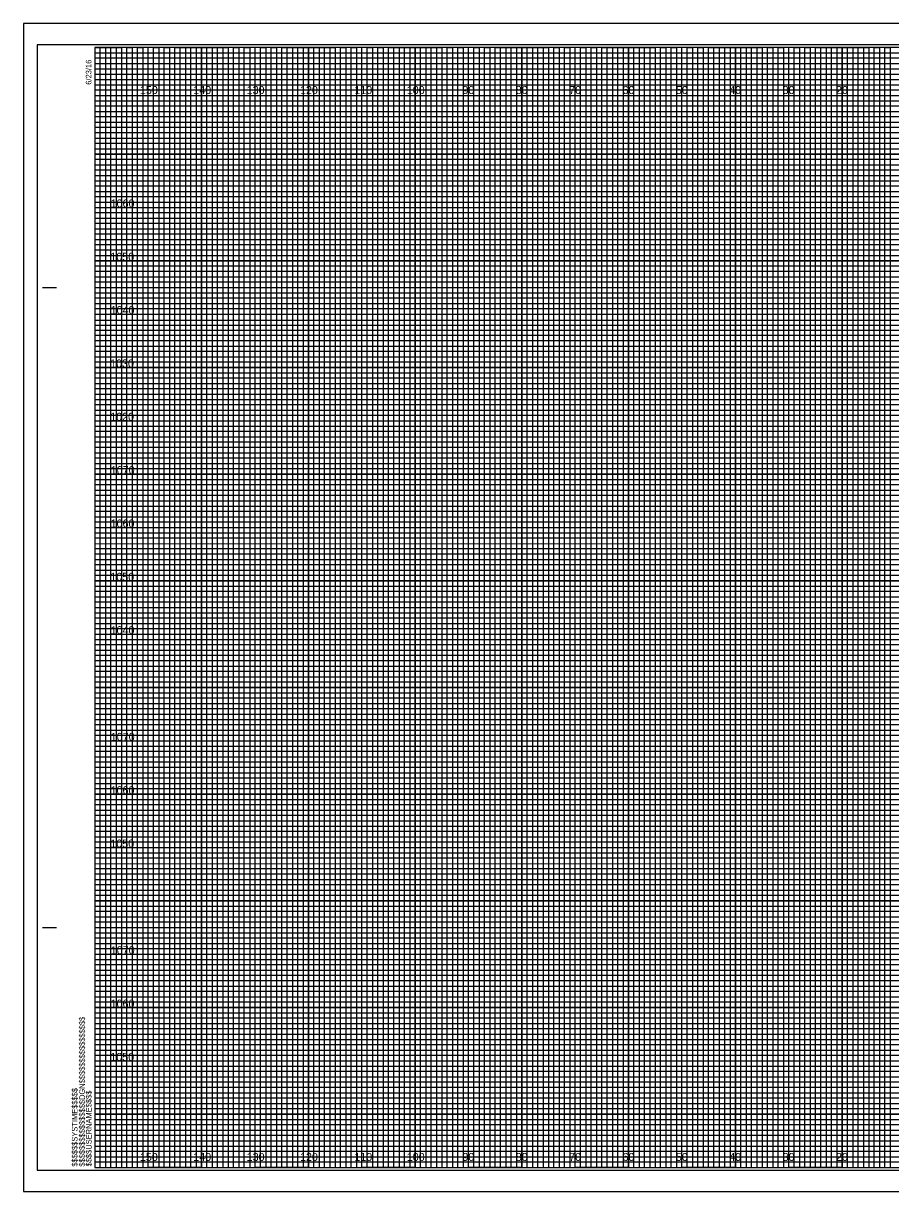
# Model space of a CAD drawing. Extents: x -13 to 323, y -5 to 215.
# Drawn here: x -13.4 to 149.1, y -4.5 to 214.5 of the extents above; entities that cross this region are included whole.
import ezdxf

# ---------------------------------------------------------------- set-up
doc = ezdxf.new("R2010")
doc.units = 0
for name, color, linetype in [('Exist Cross Section Cell', 7, 'Continuous'), ('Exist XS Center Line Elevation Label', 7, 'Continuous'), ('Exist XS Ground Line', 7, 'Continuous'), ('Prop CMT Conc Surface', 7, 'Continuous'), ('Prop CMT Concrete Structures', 7, 'Continuous'), ('Prop CMT Pvmt Course 1 CG', 7, 'Continuous'), ('Prop CMT Pvmt Course 2', 7, 'Continuous'), ('Prop CMT Pvmt Surface', 7, 'Continuous'), ('Prop CMT Slope Grass', 7, 'Continuous'), ('Prop CMT Subgrade Earthwork', 7, 'Continuous'), ('Scratch_Level_0', 7, 'Continuous')]:
    doc.layers.add(name, color=color, linetype=linetype)

msp = doc.modelspace()

# ---------------------------------------------------------------- linework, layer by layer
at = {"layer": 'Exist XS Ground Line'}
for p, q in [((323.3, 214.5), (-13.4, 214.5)), ((-13.4, 214.5), (-13.4, -4.5)), ((-13.4, -4.5), (323.3, -4.5))]:
    msp.add_line(p, q, dxfattribs=at)
at = {"layer": 'Prop CMT Conc Surface'}
msp.add_lwpolyline([(-13.4, -4.5), (323.3, -4.5), (323.3, 214.5), (-13.4, 214.5)], close=True, dxfattribs=at)
at = {"layer": 'Prop CMT Concrete Structures'}
for p, q in [((0, 209), (260, 209)), ((260, 207.98), (0, 207.98)), ((0, 207.98), (0, 207)), ((0, 207), (260, 207)), ((260, 205.89), (0, 205.89)), ((0, 205.89), (0, 204)), ((0, 204), (320, 204))]:
    msp.add_line(p, q, dxfattribs=at)
for points in [[(0, 203), (270, 203), (320, 203), (320, 202), (0, 202)], [(0, 201), (320, 201), (320, 199), (0, 199)], [(0, 198), (320, 198), (320, 197), (0, 196.98)], [(0, 196), (320, 196), (320, 194), (0, 194)], [(0, 193), (320, 193), (320, 192), (0, 192)], [(0, 191), (320, 191), (320, 189), (0, 189)], [(0, 188), (320, 188), (320, 187), (0, 187)], [(0, 186), (320, 186), (320, 184), (0, 184)], [(0, 183), (320, 183), (320, 182), (0, 182)], [(0, 181), (320, 181), (320, 179), (0, 179)], [(0, 178), (320, 178), (320, 177), (0, 177)], [(0, 176), (320, 176), (320, 173.95), (320, 173), (320, 172), (0, 172)], [(0, 174), (320, 174), (320, 173), (0, 173)], [(0, 171), (320, 171), (320, 169), (0, 169.03)], [(0, 169.03), (320, 169), (320, 168), (0, 168)], [(0, 167), (320, 167), (320, 166), (0, 166)], [(0, 164), (320, 164), (320, 163), (0, 163)], [(0, 162), (320, 162), (320, 161), (0, 161)], [(-0.07, 158.89), (320, 158.89), (320, 157.88), (-0.07, 157.88)], [(0, 157), (320, 157), (320, 156), (0, 156)], [(0, 154), (320, 154), (320, 153), (0, 153)], [(0, 152), (320, 152), (320, 151), (0, 151)], [(0, 149), (320, 149), (320, 148), (0, 148)], [(0, 147), (320, 147), (320, 146), (0, 146)], [(0, 144), (320, 144), (320, 143), (0, 143)], [(0, 142), (320, 142), (320, 141), (0, 141)], [(0, 139), (320, 139), (319.99, 137.98), (0, 138)], [(0, 137), (320, 137), (320, 136), (0, 136)], [(0, 134), (320, 134), (320, 133), (0, 133)], [(0, 132), (320, 132), (320, 131), (0, 131)], [(0, 129), (320, 129), (320, 128), (0, 128)], [(0, 127), (320, 127), (320, 126), (0, 126)], [(0, 124), (320, 124), (320, 123), (0, 123)], [(0, 122), (320, 122), (320, 121), (0, 121)], [(0, 119), (320, 119), (320, 118), (0, 118)], [(0, 116.99), (320.07, 116.91), (320, 116), (0, 116)], [(0, 114), (320, 114), (320, 113), (0, 113)], [(0, 112), (320, 112), (320, 111), (0, 111)], [(0, 109), (320, 109), (320, 108), (0, 108)], [(0, 107), (320, 107), (320, 106), (0, 106)], [(0, 104), (320, 104), (320, 103), (0, 103)], [(0, 102), (320, 102), (320, 101), (0, 101)], [(0, 99), (320, 99), (320, 98), (0, 98)], [(0, 97), (320, 97), (320, 96), (0, 96)], [(0, 94), (320, 94), (320, 93), (0, 93)], [(0, 92), (320, 92), (320, 91), (0, 91)], [(0, 89), (320, 89), (320, 88), (0, 88)], [(0, 87), (320, 87), (320, 86), (0, 86)], [(0, 84), (320, 84), (320, 83), (0, 83)], [(0, 82), (320, 82), (320, 81), (0, 81)], [(0, 79), (320, 79), (319.99, 77.98), (0, 78)], [(0, 77), (320, 77), (320, 76), (0, 76)], [(0, 74), (320, 74), (320, 73), (0, 73)], [(0, 72), (320, 72), (320, 71), (0, 71)], [(0, 69), (320, 69), (320, 68), (0, 68)], [(0, 67), (320, 67), (320, 66), (0, 66)], [(0, 64), (320, 64), (320, 63), (0, 63)], [(0, 62), (320, 62), (320, 61), (0, 61)], [(0, 59), (320, 59), (320, 58), (0, 58)], [(0, 56.99), (320.07, 56.91), (320, 56), (0, 56)], [(0, 54), (320, 54), (320, 53), (0, 53)], [(0, 52), (320, 52), (320, 51), (0, 51)], [(0, 49), (320, 49), (320, 48), (0, 48)], [(0, 47), (320, 47), (320, 46), (0, 46)], [(0, 44), (320, 44), (320, 43), (0, 43)], [(0, 42), (320, 42), (320, 41), (0, 41)], [(0, 39), (320, 39), (320, 38), (0, 38)], [(0, 37), (320, 37), (320, 36), (0, 36)], [(0, 34), (320, 34), (320, 33), (0, 33)], [(0, 32), (320, 32), (320, 31), (0, 31)], [(0, 29), (320, 29), (320, 28), (0, 28)], [(0, 27), (320, 27), (320, 26), (0, 26)], [(0, 24), (320, 24), (320, 23), (0, 23)], [(0, 22), (320, 22), (320, 21), (0, 21)], [(0, 19), (320, 19), (320, 18), (0, 18)], [(0, 17), (320, 17), (320, 16), (0, 16)], [(0, 14), (320, 14), (320, 13), (0, 13)], [(0, 12), (320, 12), (320, 11), (0, 11)], [(0, 9), (320, 9), (320, 8), (0, 8)], [(0, 7), (320, 7), (320, 6), (0, 6)], [(0, 4), (320, 4), (320, 3), (0, 3)], [(0, 2), (320, 2), (320, 1), (0, 1)]]:
    msp.add_lwpolyline(points, dxfattribs=at)
at = {"layer": 'Prop CMT Pvmt Course 1 CG'}
for points in [[(0, 0), (1, 0), (1, 210), (2, 210), (2, 0)], [(2, 0), (3, 0), (3, 210), (4, 210), (4, 0)], [(5, 0), (6, 0), (6, 210), (7, 210), (7, 0)], [(7, 0), (8, 0), (8, 210), (9, 210), (9, 0)], [(10, 0), (11, 0), (11, 210), (12, 210), (12, 0)], [(12, 0), (13, 0), (13, 210), (14, 210), (14, 0)], [(15, 0), (16, 0), (16, 210), (17, 210), (17, 0)], [(17, 0), (18, 0), (18, 210), (19, 210), (19, 0)], [(20, 0), (21, 0), (21, 210), (22, 210), (22, 0)], [(22, 0), (23, 0), (23, 210), (24, 210), (24, 0)], [(25, 0), (26, 0), (26, 210), (27, 210), (27, 0)], [(27, 0), (28, 0), (28, 210), (29, 210), (29, 0)], [(30, 0), (31, 0), (31, 210), (32, 210), (32, 0)], [(32, 0), (33, 0), (33, 210), (34, 210), (34, 0)], [(35, 0), (36, 0), (36, 210), (37, 210), (37, 0)], [(37, 0), (38, 0), (38, 210), (39, 210), (39, 0)], [(40, 0), (41, 0), (41, 210), (42, 210), (42, 0)], [(42, 0), (43, 0), (43, 210), (44, 210), (44, 0)], [(45, 0), (46, 0), (46, 210), (47, 210), (47, 0)], [(47, 0), (48, 0), (48, 210), (49, 210), (49, 0)], [(50, 0), (51, 0), (51, 210), (52, 210), (52, 0)], [(52, 0), (53, 0), (53, 210), (54, 210), (54, 0)], [(55, 0), (56, 0), (56, 210), (57, 210), (57, 0)], [(57, 0), (58, 0), (58, 210), (59, 210), (59, 0)], [(60, 0), (61, 0), (61, 210), (62, 210), (62, 0)], [(62, 0), (63, 0), (63, 210), (64, 210), (64, 0)], [(65, 0), (66, 0), (66, 210), (67, 210), (67, 0)], [(67, 0), (68, 0), (68, 210), (69, 210), (69, 0)], [(70, 0), (71, 0), (71, 210), (72, 210), (72, 0)], [(72, 0), (73, 0), (73, 210), (74, 210), (74, 0)], [(75, 0), (76, 0), (76, 210), (77, 210), (77, 0)], [(77, 0), (78, 0), (78, 210), (79, 210), (79, 0)], [(80, 0), (81, 0), (81, 210), (82, 210), (82, 0)], [(82, 0), (83, 0), (83, 210), (84, 210), (84, 0)], [(85, 0), (86, 0), (86, 210), (87, 210), (87, 0)], [(87, 0), (88, 0), (88, 210), (89, 210), (89, 0)], [(90, 0), (91, 0), (91, 210), (92, 210), (92, 0)], [(92, 0), (93, 0), (93, 210), (94, 210), (94, 0)], [(95, 0), (96, 0), (96, 210), (97, 210), (97, 0)], [(97, 0), (98, 0), (98, 210), (99, 210), (99, 0)], [(100, 0), (101, 0), (101, 210), (102, 210), (102, 0)], [(102, 0), (103, 0), (103, 210), (104, 210), (104, 0)], [(105, 0), (106, 0), (106, 210), (107, 210), (107, 0)], [(107, 0), (108, 0), (108, 210), (109, 210), (109, 0)], [(110, 0), (111, 0), (111, 210), (112, 210), (112, 0)], [(112, 0), (113, 0), (113, 210), (114, 210), (114, 0)], [(115, 0), (116, 0), (116, 210), (117, 210), (117, 0)], [(117, 0), (118, 0), (118, 210), (119, 210), (119, 0)], [(120, 0), (121, 0), (121, 210), (122, 210), (122, 0)], [(122, 0), (123, 0), (123, 210), (124, 210), (124, 0)], [(125, 0), (126, 0), (126, 210), (127, 210), (127, 0)], [(127, 0), (128, 0), (128, 210), (129, 210), (129, 0)], [(130, 0), (131, 0), (131, 210), (132, 210), (132, 0)], [(132, 0), (133, 0), (133, 210), (134, 210), (134, 0)], [(135, 0), (136, 0), (136, 210), (137, 210), (137, 0)], [(137, 0), (138, 0), (138, 210), (139, 210), (139, 0)], [(140, 0), (141, 0), (141, 210), (142, 210), (142, 0)], [(142, 0), (143, 0), (143, 210), (144, 210), (144, 0)], [(145, 0), (146, 0), (146, 210), (147, 210), (147, 0)], [(147, 0), (148, 0), (148, 210), (149, 210), (149, 0)]]:
    msp.add_lwpolyline(points, dxfattribs=at)
at = {"layer": 'Prop CMT Pvmt Course 2'}
for points in [[(0, 210), (5, 210), (5, 0), (15, 0), (15, 210), (25, 210), (25, 0), (35, 0), (35, 210), (45, 210), (45, 0), (55, 0), (55, 210), (65, 210), (65, 0), (75, 0), (75, 210), (85, 210), (85, 0), (95, 0), (95, 210), (105, 210), (105, 0), (115, 0), (115, 210), (125, 210), (125, 0), (135, 0), (135, 210), (145, 210), (145, 0), (155, 0)], [(0, 205), (275, 205)], [(0, 185), (320, 185), (320, 195), (0, 195)], [(0, 165), (320, 165), (320, 175), (0, 175)], [(0, 145), (320, 145), (320, 155), (0, 155)], [(0, 125), (320, 125), (320, 135), (0, 135)], [(0, 105), (320, 105), (320, 115), (0, 115)], [(0, 85), (320, 85), (320, 95), (0, 95)], [(0, 65), (320, 65), (320, 75), (0, 75)], [(0, 45), (320, 45), (320, 55), (0, 55)], [(0, 25), (320, 25), (320, 35), (0, 35)], [(0, 5), (320, 5), (320, 15), (0, 15)]]:
    msp.add_lwpolyline(points, dxfattribs=at)
at = {"layer": 'Prop CMT Pvmt Surface'}
for p, q in [((-9.8, 165), (-7.3, 165)), ((-9.7, 165), (-7.2, 165)), ((-9.8, 45), (-7.3, 45)), ((-9.7, 45), (-7.2, 45)), ((0, 0), (0, 0)), ((0, 0), (0, 0)), ((0, 0), (0, 0)), ((0, 0), (0, 0)), ((0, 0), (0, 0)), ((0, 0), (0, 0)), ((0, 0), (0, 0))]:
    msp.add_line(p, q, dxfattribs=at)
msp.add_lwpolyline([(320, 210), (0, 210), (0, 0), (320, 0)], close=True, dxfattribs=at)
at = {"layer": 'Prop CMT Slope Grass'}
for p, q in [((10, 0), (10, 210)), ((20, 0), (20, 210)), ((30, 0), (30, 210)), ((40, 0), (40, 210)), ((50, 0), (50, 210)), ((60, 0), (60, 210)), ((70, 0), (70, 210)), ((80, 0), (80, 210)), ((90, 0), (90, 210)), ((100, 0), (100, 210)), ((110, 0), (110, 210)), ((120, 0), (120, 210)), ((130, 0), (130, 210)), ((140, 0), (140, 210)), ((0, 200), (320, 200)), ((0, 190), (320, 190)), ((0, 180), (320, 180)), ((0, 170), (320, 170)), ((0, 160), (320, 160)), ((0, 150), (320, 150)), ((0, 140), (320, 140)), ((0, 130), (320, 130)), ((0, 120), (320, 120)), ((0, 110), (320, 110)), ((0, 100), (320, 100)), ((0, 90), (320, 90)), ((0, 80), (320, 80)), ((0, 70), (320, 70)), ((0, 60), (320, 60)), ((0, 50), (320, 50)), ((0, 40), (320, 40)), ((0, 30), (320, 30)), ((0, 20), (320, 20)), ((0, 10), (320, 10))]:
    msp.add_line(p, q, dxfattribs=at)
at = {"layer": 'Prop CMT Subgrade Earthwork'}
msp.add_lwpolyline([(-10.8, -0.5), (322.4, -0.5), (322.4, 210.5), (-10.8, 210.5)], close=True, dxfattribs=at)
at = {"layer": 'Scratch_Level_0'}
for p, q in [((10, 210), (0, 210)), ((10, 0), (10, 210)), ((30, 210), (20, 210)), ((20, 210), (20, 0)), ((30, 0), (30, 210)), ((50, 210), (40, 210)), ((40, 210), (40, 0)), ((50, 0), (50, 210)), ((70, 210), (60, 210)), ((60, 210), (60, 0)), ((70, 0), (70, 210)), ((90, 210), (80, 210)), ((80, 210), (80, 0)), ((90, 0), (90, 210)), ((110, 210), (100, 210)), ((100, 210), (100, 0)), ((110, 0), (110, 210)), ((130, 210), (120, 210)), ((120, 210), (120, 0)), ((130, 0), (130, 210)), ((150, 210), (140, 210)), ((140, 210), (140, 0)), ((20, 0), (10, 0)), ((40, 0), (30, 0)), ((60, 0), (50, 0)), ((80, 0), (70, 0)), ((100, 0), (90, 0)), ((120, 0), (110, 0)), ((140, 0), (130, 0))]:
    msp.add_line(p, q, dxfattribs=at)
for points in [[(0, 200), (320, 200), (320, 190), (0, 190)], [(0, 180), (320, 180), (320, 170), (0, 170)], [(0, 160), (320, 160), (320, 150), (0, 150)], [(0, 140), (320, 140), (320, 130), (0, 130)], [(0, 120), (320, 120), (320, 110), (0, 110)], [(0, 100), (320, 100), (320, 90), (0, 90)], [(0, 80), (320, 80), (320, 70), (0, 70)], [(0, 60), (320, 60), (320, 50), (0, 50)], [(0, 40), (320, 40), (320, 30), (0, 30)], [(0, 20), (320, 20), (320, 10), (0, 10)]]:
    msp.add_lwpolyline(points, dxfattribs=at)

# ---------------------------------------------------------------- texts
at = {"layer": 'Exist Cross Section Cell'}
for s, p in [('150', (8.44, 201.25)), ('140', (18.44, 201.25)), ('130', (28.44, 201.25)), ('120', (38.44, 201.25)), ('110', (48.62, 201.25)), ('100', (58.44, 201.25)), ('90', (68.86, 201.25)), ('80', (78.86, 201.25)), ('70', (88.86, 201.25)), ('60', (98.86, 201.25)), ('50', (108.86, 201.25)), ('40', (118.86, 201.25)), ('30', (128.86, 201.25)), ('20', (138.86, 201.25)), ('150', (8.44, 1.25)), ('140', (18.44, 1.25)), ('130', (28.44, 1.25)), ('120', (38.44, 1.25)), ('110', (48.62, 1.25)), ('100', (58.44, 1.25)), ('90', (68.86, 1.25)), ('80', (78.86, 1.25)), ('70', (88.86, 1.25)), ('60', (98.86, 1.25)), ('50', (108.86, 1.25)), ('40', (118.86, 1.25)), ('30', (128.86, 1.25)), ('20', (138.86, 1.25))]:
    msp.add_text(s, height=1.5, dxfattribs=at).set_placement(p)
at = {"layer": 'Exist XS Center Line Elevation Label'}
for s, p in [('1060', (2.95, 180)), ('1050', (2.9, 170)), ('1040', (2.95, 160)), ('1030', (2.86, 150)), ('1020', (2.87, 140)), ('1070', (2.98, 130)), ('1060', (2.95, 120)), ('1050', (2.9, 110)), ('1040', (2.95, 100)), ('1070', (2.98, 80)), ('1060', (2.95, 70)), ('1050', (2.9, 60)), ('1070', (2.98, 40)), ('1060', (2.95, 30)), ('1050', (2.9, 20))]:
    msp.add_text(s, height=1.5, dxfattribs=at).set_placement(p)
at = {"layer": 'Prop CMT Pvmt Surface'}
for s, p in [('6/23/16', (-0.65, 203)), ('$$$$$$$$$$$$$$$$DGN$$$$$$$$$$$$$$$$', (-1.88, 0.18)), ('$$$$$$SYSTIME$$$$$', (-3.26, 0.18)), ('$$$$USERNAME$$$$', (-0.62, 0.23))]:
    msp.add_text(s, height=1.05, rotation=90, dxfattribs=at).set_placement(p)

doc.saveas('drawing.dxf')
